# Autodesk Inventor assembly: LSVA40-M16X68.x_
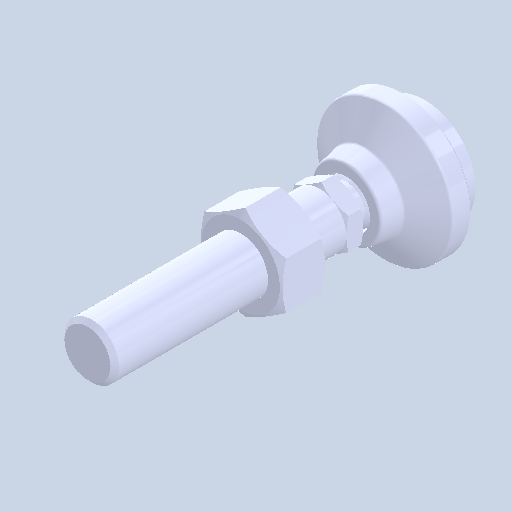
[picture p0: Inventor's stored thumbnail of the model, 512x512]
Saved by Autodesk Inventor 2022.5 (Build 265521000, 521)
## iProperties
Created: 2024-08
Part Number: LSVA40-M16X68.x_
Document SubType Name: Assembly
Designer: ImaoCorp
Author: ImaoCorp
Sending System: SOLIDWORKS 2022-2022290
MC: AMD64
MC_MODEL: Intel64 Family 6 Model 60 Stepping 3, GenuineIntel
OS: Windows_NT
FRU: Parasolid Version 33.1, build 260,  4-25-2022
FORMAT: text
GUISE: transmit
KEY: FILELSVA40-M16X68.x_t
DATE: Fri Aug 23 16:07:51 2024
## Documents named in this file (4)
- X:\14_SW2022-Inv2022\06_2024-10新製品(SME)\ELS_データ\l\lsva40-m16x68\LSVA40-M16X68.x_.iam
- X:\14_SW2022-Inv2022\06_2024-10新製品(SME)\ELS_データ\l\lsva40-m16x68\LSVA40-M16X68_01.ipt
- X:\14_SW2022-Inv2022\06_2024-10新製品(SME)\ELS_データ\l\lsva40-m16x68\LSVA40-M16X68_02.ipt
- X:\14_SW2022-Inv2022\06_2024-10新製品(SME)\ELS_データ\l\lsva40-m16x68\LSVA40-M16X68_03.ipt
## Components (3 placed, 3 different names)
1. LSVA40-M16X68_01
2. LSVA40-M16X68_02
3. LSVA40-M16X68_03
